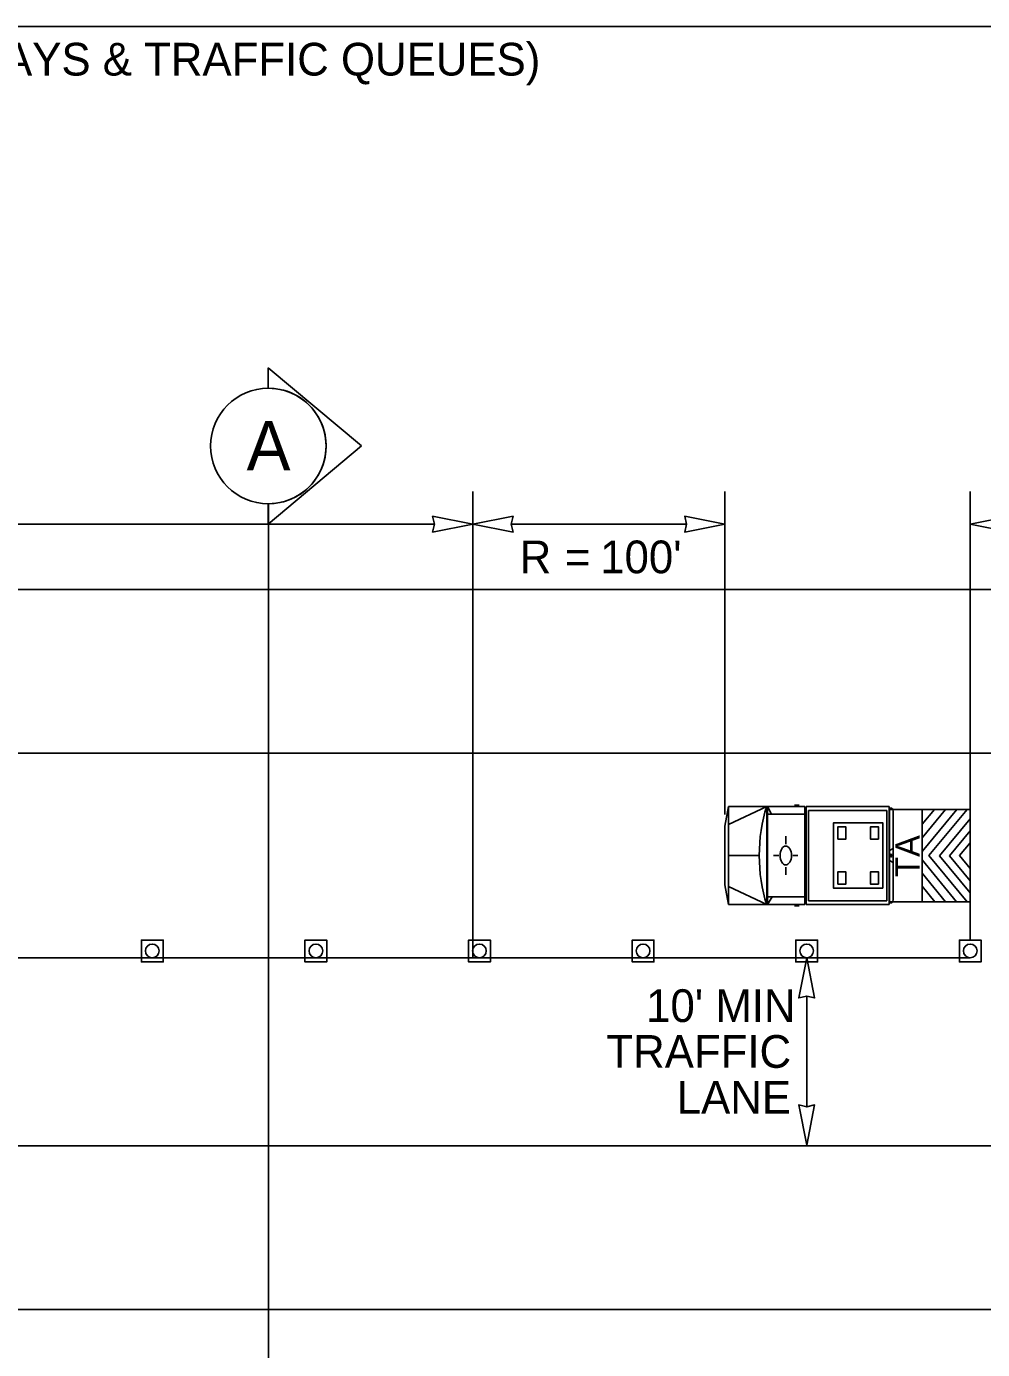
# Model space of a CAD drawing. Extents: x 99999.1 to 100095.7, y 99995 to 100010.7.
# Drawn here: x 100048.842 to 100051.18, y 100005.634 to 100008.869 of the extents above; entities that cross this region are included whole.
import ezdxf

# ---------------------------------------------------------------- set-up
doc = ezdxf.new("R2010")
doc.units = 0
for name, color, linetype in [('RD_ED_ShoulderPavedEdge', 7, 'Continuous'), ('RD_MK_LineEdgeWhite', 7, 'Continuous'), ('RD_MK_LineSkipCenter', 7, 'Continuous'), ('SH_TI_WZSectionCut', 7, 'Continuous'), ('TR_WZ_TrafficCone', 7, 'Continuous'), ('TR_WZ_TransportableAttenuator', 7, 'Continuous'), ('TR_WZ_WorkZoneDetails', 7, 'Continuous'), ('TR_WZ_WorkZoneTextCurrent', 7, 'Continuous')]:
    doc.layers.add(name, color=color, linetype=linetype)

msp = doc.modelspace()

# ---------------------------------------------------------------- linework, layer by layer
at = {"layer": 'RD_ED_ShoulderPavedEdge'}
for p, q in [((100040.1076, 100007.4923), (100055.6424, 100007.4923)), ((100040.1076, 100005.7323), (100055.6424, 100005.7323))]:
    msp.add_line(p, q, dxfattribs=at)
at = {"layer": 'RD_MK_LineEdgeWhite'}
for p, q in [((100040.1076, 100007.0923), (100055.6424, 100007.0923)), ((100040.1076, 100006.1323), (100055.6424, 100006.1323))]:
    msp.add_line(p, q, dxfattribs=at)
at = {"layer": 'RD_MK_LineSkipCenter'}
msp.add_lwpolyline([(100051.15, 100006.5923), (100043.4767, 100006.5923)], dxfattribs=at)
at = {"layer": 'SH_TI_WZSectionCut'}
for p, q in [((100049.4337, 100007.9847), (100049.4337, 100008.0346)), ((100049.4337, 100008.0346), (100049.6619, 100007.8435)), ((100049.6619, 100007.8435), (100049.4337, 100007.6523)), ((100049.4337, 100007.6523), (100049.4337, 100007.7022)), ((100049.4338, 100007.7022), (100049.4338, 100005.5723))]:
    msp.add_line(p, q, dxfattribs=at)
msp.add_circle((100049.4338, 100007.8435), 0.1412, dxfattribs=at)
msp.add_arc((100049.4338, 100007.8435), 0.1412, 269.9978, 90.0022, dxfattribs=at)
at = {"layer": 'TR_WZ_TrafficCone'}
for points in [[(100049.1234, 100006.6357), (100049.1767, 100006.6357), (100049.1767, 100006.5823), (100049.1234, 100006.5823), (100049.1234, 100006.6357)], [(100049.1234, 100006.5823), (100049.1767, 100006.5823), (100049.1767, 100006.6357), (100049.1234, 100006.6357), (100049.1234, 100006.5823)], [(100049.5234, 100006.6357), (100049.5767, 100006.6357), (100049.5767, 100006.5823), (100049.5234, 100006.5823), (100049.5234, 100006.6357)], [(100049.5234, 100006.5823), (100049.5767, 100006.5823), (100049.5767, 100006.6357), (100049.5234, 100006.6357), (100049.5234, 100006.5823)], [(100049.9234, 100006.6357), (100049.9767, 100006.6357), (100049.9767, 100006.5823), (100049.9234, 100006.5823), (100049.9234, 100006.6357)], [(100049.9234, 100006.5823), (100049.9767, 100006.5823), (100049.9767, 100006.6357), (100049.9234, 100006.6357), (100049.9234, 100006.5823)], [(100050.3234, 100006.6357), (100050.3767, 100006.6357), (100050.3767, 100006.5823), (100050.3234, 100006.5823), (100050.3234, 100006.6357)], [(100050.3234, 100006.5823), (100050.3767, 100006.5823), (100050.3767, 100006.6357), (100050.3234, 100006.6357), (100050.3234, 100006.5823)], [(100050.7234, 100006.6357), (100050.7767, 100006.6357), (100050.7767, 100006.5823), (100050.7234, 100006.5823), (100050.7234, 100006.6357)], [(100050.7234, 100006.5823), (100050.7767, 100006.5823), (100050.7767, 100006.6357), (100050.7234, 100006.6357), (100050.7234, 100006.5823)], [(100051.1766, 100006.6357), (100051.1233, 100006.6357), (100051.1233, 100006.5823), (100051.1766, 100006.5823), (100051.1766, 100006.6357)], [(100051.1766, 100006.5823), (100051.1233, 100006.5823), (100051.1233, 100006.6357), (100051.1766, 100006.6357), (100051.1766, 100006.5823)]]:
    msp.add_lwpolyline(points, dxfattribs=at)
for centre in [(100049.15, 100006.609), (100049.55, 100006.609), (100049.95, 100006.609), (100050.35, 100006.609), (100050.75, 100006.609), (100051.15, 100006.609)]:
    msp.add_circle(centre, 0.0167, dxfattribs=at)
at = {"layer": 'TR_WZ_TransportableAttenuator'}
for p, q in [((100050.7203, 100006.9656), (100050.7315, 100006.9656)), ((100050.5592, 100006.9623), (100050.55, 100006.9138)), ((100050.5592, 100006.7223), (100050.5592, 100006.9623)), ((100050.5592, 100006.9623), (100050.7457, 100006.9623)), ((100050.5592, 100006.9183), (100050.6525, 100006.9623)), ((100050.6525, 100006.7223), (100050.6525, 100006.9623)), ((100050.6541, 100006.7223), (100050.6541, 100006.9623)), ((100050.664, 100006.9437), (100050.6541, 100006.9623)), ((100050.6541, 100006.9437), (100050.7457, 100006.9437)), ((100050.7457, 100006.7223), (100050.7457, 100006.9623)), ((100050.9516, 100006.9623), (100050.7484, 100006.9623)), ((100050.7484, 100006.7223), (100050.7484, 100006.9623)), ((100050.9458, 100006.9527), (100050.7542, 100006.9527)), ((100050.7542, 100006.7318), (100050.7542, 100006.9527)), ((100050.9458, 100006.7318), (100050.9458, 100006.9527)), ((100050.9516, 100006.7223), (100050.9516, 100006.9623)), ((100050.9516, 100006.9546), (100051.0321, 100006.9546)), ((100050.9516, 100006.7298), (100050.9516, 100006.9546)), ((100050.9567, 100006.9583), (100050.9523, 100006.9583)), ((100050.9523, 100006.7262), (100050.9523, 100006.9583)), ((100050.9611, 100006.7335), (100050.9611, 100006.951)), ((100051.0321, 100006.8522), (100051.1173, 100006.9548)), ((100051.0321, 100006.9185), (100051.0628, 100006.9548)), ((100051.0897, 100006.9548), (100051.0321, 100006.8853)), ((100051.1173, 100006.9548), (100051.0321, 100006.8522)), ((100051.0321, 100006.8853), (100051.0897, 100006.9548)), ((100051.0628, 100006.9548), (100051.0321, 100006.9185)), ((100051.0321, 100006.9546), (100051.0321, 100006.7294)), ((100051.1423, 100006.9548), (100051.0487, 100006.842)), ((100051.0487, 100006.842), (100051.1423, 100006.9548)), ((100051.0628, 100006.9548), (100051.0897, 100006.9548)), ((100051.0897, 100006.9548), (100051.0628, 100006.9548)), ((100051.0749, 100006.8414), (100051.15, 100006.9319)), ((100051.15, 100006.9319), (100051.0749, 100006.8414)), ((100051.1173, 100006.9548), (100051.1423, 100006.9548)), ((100051.1423, 100006.9548), (100051.1173, 100006.9548)), ((100051.15, 100006.9319), (100051.15, 100006.9025)), ((100051.15, 100006.9025), (100051.15, 100006.9319)), ((100050.55, 100006.7707), (100050.55, 100006.9138)), ((100051.0321, 100006.8853), (100051.0321, 100006.9185)), ((100051.0321, 100006.9185), (100051.0321, 100006.8853)), ((100051.15, 100006.9025), (100051.099, 100006.8411)), ((100051.099, 100006.8411), (100051.15, 100006.9025)), ((100050.6989, 100006.8898), (100050.6989, 100006.8704)), ((100051.1239, 100006.8419), (100051.15, 100006.8733)), ((100051.15, 100006.8733), (100051.1239, 100006.8419)), ((100051.15, 100006.8733), (100051.15, 100006.8109)), ((100051.15, 100006.8109), (100051.15, 100006.8733)), ((100050.5592, 100006.8423), (100050.6341, 100006.8423)), ((100050.6691, 100006.8421), (100050.6816, 100006.8422)), ((100050.7128, 100006.8427), (100050.7128, 100006.8427)), ((100050.7287, 100006.8421), (100050.7162, 100006.8422)), ((100050.9611, 100006.8592), (100050.9523, 100006.8547)), ((100050.9587, 100006.8423), (100050.9546, 100006.8423)), ((100050.9567, 100006.8389), (100050.9567, 100006.8456)), ((100051.0321, 100006.8321), (100051.0321, 100006.8522)), ((100051.0321, 100006.8522), (100051.0321, 100006.8321)), ((100051.0487, 100006.842), (100051.1422, 100006.7294)), ((100051.1422, 100006.7294), (100051.0487, 100006.842)), ((100051.15, 100006.7508), (100051.0749, 100006.8414)), ((100051.0749, 100006.8414), (100051.15, 100006.7508)), ((100051.099, 100006.8411), (100051.15, 100006.78)), ((100051.15, 100006.78), (100051.099, 100006.8411)), ((100051.15, 100006.8109), (100051.1239, 100006.8419)), ((100051.1239, 100006.8419), (100051.15, 100006.8109)), ((100050.6989, 100006.7947), (100050.6989, 100006.8141)), ((100050.9611, 100006.8254), (100050.9523, 100006.8299)), ((100051.1167, 100006.7294), (100051.0321, 100006.8321)), ((100051.0321, 100006.8321), (100051.1167, 100006.7294)), ((100050.5592, 100006.7223), (100050.55, 100006.7707)), ((100051.0321, 100006.7989), (100051.0891, 100006.7294)), ((100051.0321, 100006.7675), (100051.0321, 100006.7989)), ((100051.0891, 100006.7294), (100051.0321, 100006.7989)), ((100051.0321, 100006.7989), (100051.0321, 100006.7675)), ((100051.15, 100006.78), (100051.15, 100006.7508)), ((100051.15, 100006.7508), (100051.15, 100006.78)), ((100050.5592, 100006.7662), (100050.6525, 100006.7223)), ((100050.6541, 100006.7223), (100050.666, 100006.7409)), ((100050.6541, 100006.7409), (100050.7457, 100006.7409)), ((100051.0637, 100006.7294), (100051.0321, 100006.7675)), ((100051.0321, 100006.7675), (100051.0637, 100006.7294)), ((100050.5592, 100006.7223), (100050.7457, 100006.7223)), ((100050.7203, 100006.7189), (100050.7315, 100006.7189)), ((100050.9516, 100006.7223), (100050.7484, 100006.7223)), ((100050.9458, 100006.7318), (100050.7542, 100006.7318)), ((100050.9516, 100006.7294), (100051.0321, 100006.7294)), ((100050.9567, 100006.7262), (100050.9523, 100006.7262)), ((100051.0891, 100006.7294), (100051.0637, 100006.7294)), ((100051.0637, 100006.7294), (100051.0891, 100006.7294)), ((100051.1422, 100006.7294), (100051.1167, 100006.7294)), ((100051.1167, 100006.7294), (100051.1422, 100006.7294))]:
    msp.add_line(p, q, dxfattribs=at)
for points in [[(100051.0321, 100006.9548), (100051.15, 100006.9548), (100051.15, 100006.7294), (100051.0321, 100006.7294)], [(100050.9358, 100006.7623), (100050.8158, 100006.7623), (100050.8158, 100006.9223), (100050.9358, 100006.9223)], [(100050.8258, 100006.8823), (100050.8458, 100006.8823), (100050.8458, 100006.9123), (100050.8258, 100006.9123)], [(100050.9258, 100006.8823), (100050.9058, 100006.8823), (100050.9058, 100006.9123), (100050.9258, 100006.9123)], [(100050.8258, 100006.7723), (100050.8458, 100006.7723), (100050.8458, 100006.8023), (100050.8258, 100006.8023)], [(100050.9258, 100006.7723), (100050.9058, 100006.7723), (100050.9058, 100006.8023), (100050.9258, 100006.8023)]]:
    msp.add_lwpolyline(points, close=True, dxfattribs=at)
msp.add_lwpolyline([(100051.0321, 100006.7294), (100051.15, 100006.7294), (100051.15, 100006.9548), (100051.0321, 100006.9546)], dxfattribs=at)
for centre, major_axis, start_param, end_param in [((100050.7857, 100006.8423), (0, -0.2519), 4.215852, 5.209111), ((100050.9567, 100006.951), (0, 0.00732), 4.712389, 6.283185), ((100050.9567, 100006.7335), (0, -0.00732), 6.283185, 7.853982)]:
    msp.add_ellipse(centre, major_axis=major_axis, ratio=0.60201, start_param=start_param, end_param=end_param, dxfattribs=at)
for centre, major_axis in [((100050.6989, 100006.8423), (0, 0.0231)), ((100050.9567, 100006.8423), (0, 0.00338))]:
    msp.add_ellipse(centre, major_axis=major_axis, ratio=0.60201, dxfattribs=at)
at = {"layer": 'TR_WZ_WorkZoneDetails'}
for p, q in [((100051.3796, 100008.8691), (100044.3704, 100008.8691)), ((100049.9338, 100007.4923), (100049.9338, 100007.7323)), ((100050.5501, 100006.9423), (100050.5501, 100007.7323)), ((100051.15, 100006.6357), (100051.15, 100007.7323)), ((100045.2437, 100007.6523), (100049.84, 100007.6523)), ((100050.4563, 100007.6523), (100050.0275, 100007.6523)), ((100050.75, 100006.2278), (100050.75, 100006.4986))]:
    msp.add_line(p, q, dxfattribs=at)
for points in [[(100049.9338, 100007.6523), (100049.8355, 100007.6331), (100049.84, 100007.6523), (100049.8355, 100007.6716)], [(100049.9338, 100007.6523), (100050.032, 100007.6331), (100050.0275, 100007.6523), (100050.032, 100007.6716)], [(100050.5501, 100007.6523), (100050.4518, 100007.6331), (100050.4563, 100007.6523), (100050.4518, 100007.6716)], [(100051.15, 100007.6523), (100051.2483, 100007.6331), (100051.2437, 100007.6523), (100051.2483, 100007.6716)], [(100045.15, 100007.4923), (100045.15, 100006.5923), (100049.9338, 100006.5923), (100049.9338, 100007.4923)], [(100050.75, 100006.5923), (100050.7308, 100006.4941), (100050.75, 100006.4986), (100050.7693, 100006.4941)], [(100050.75, 100006.1341), (100050.7308, 100006.2324), (100050.75, 100006.2278), (100050.7693, 100006.2324)]]:
    msp.add_lwpolyline(points, close=True, dxfattribs=at)

# ---------------------------------------------------------------- texts
at = {"layer": 'SH_TI_WZSectionCut'}
msp.add_text('A', height=0.12, rotation=359.99, dxfattribs=at).set_placement((100049.3808, 100007.7843))
at = {"layer": 'TR_WZ_TransportableAttenuator'}
msp.add_text('TA', height=0.06, rotation=90, dxfattribs=at).set_placement((100051.0266, 100006.7896))
at = {"layer": 'TR_WZ_WorkZoneTextCurrent'}
for s, p in [('(MINIMIZE DISTANCE BETWEEN MAINLINE FLAGGERS TO MINIMIZE DELAYS & TRAFFIC QUEUES)', (100045.0644, 100008.7491)), ('R', (100050.0483, 100007.5323)), ("100'", (100050.2452, 100007.5323)), ('=', (100050.1588, 100007.5323)), ("10' MIN", (100050.3575, 100006.4352)), ('TRAFFIC', (100050.2604, 100006.3232)), ('LANE', (100050.4323, 100006.2112))]:
    msp.add_text(s, height=0.08, dxfattribs=at).set_placement(p)

doc.saveas('drawing.dxf')
